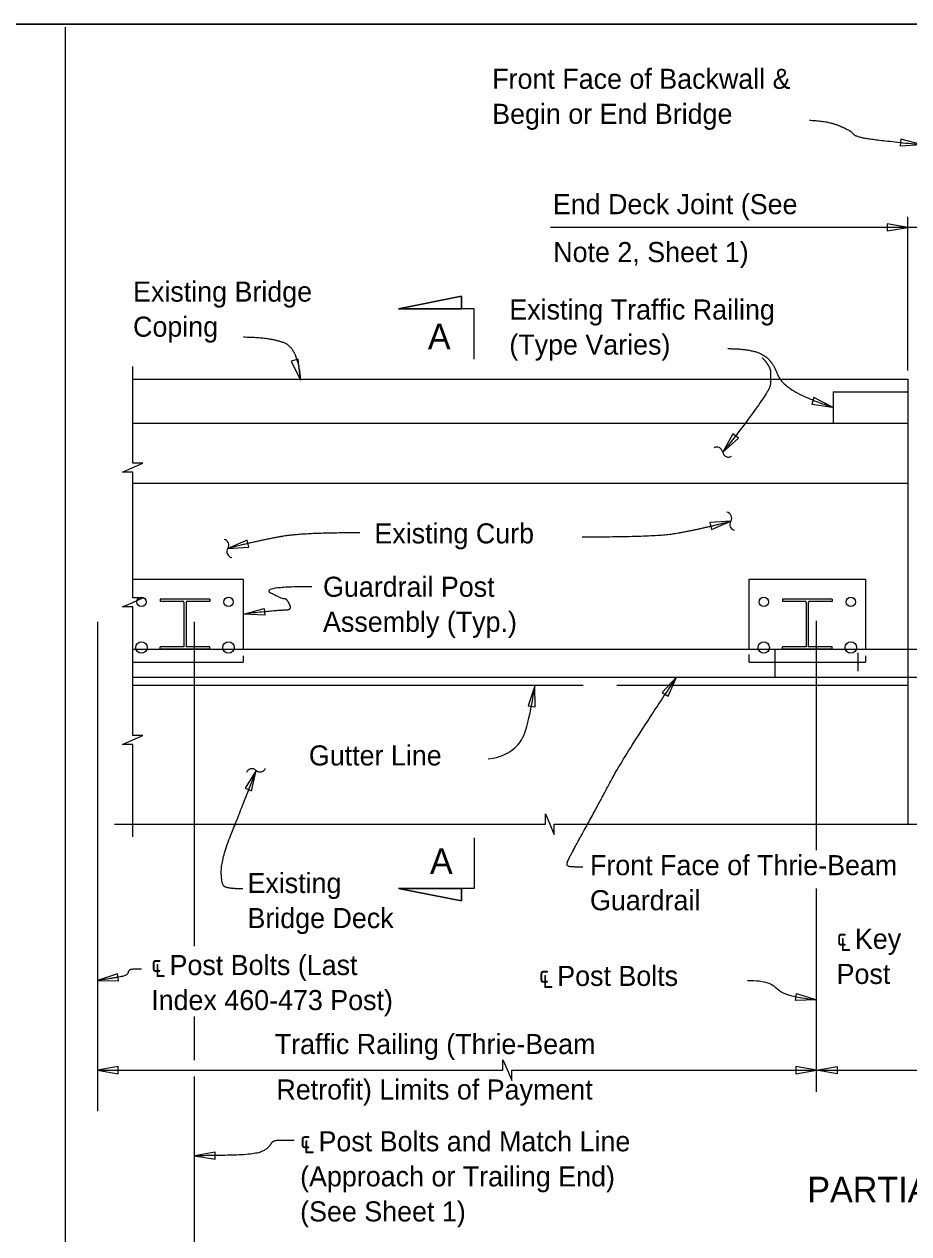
# Model space of a CAD drawing. Extents: x 0 to 41.1, y 0 to 25.9.
# Drawn here: x 18.69 to 27.57, y 13.8 to 25.95 of the extents above; entities that cross this region are included whole.
import ezdxf

# ---------------------------------------------------------------- set-up
doc = ezdxf.new("R2010")
doc.units = 0
for name, color, linetype in [('Dimension', 7, 'Continuous'), ('ExistSuperStruct', 7, 'Continuous'), ('Miscellaneous', 7, 'Continuous'), ('Miscellaneous1', 7, 'Continuous'), ('SteelMisc', 7, 'Continuous'), ('TextStructures', 7, 'Continuous')]:
    doc.layers.add(name, color=color, linetype=linetype)

msp = doc.modelspace()

# ---------------------------------------------------------------- linework, layer by layer
at = {"layer": 'Dimension'}
for p, q in [((19.1, 25.915), (19.1, -0.024)), ((27.565, 22.467), (27.565, 24.011)), ((28.073, 23.906), (23.974, 23.906)), ((22.45, 23.088), (23.083, 23.215)), ((23.083, 23.215), (23.083, 23.088)), ((23.209, 23.088), (22.45, 23.088)), ((23.209, 22.582), (23.209, 23.088)), ((26.646, 17.652), (26.646, 19.956)), ((23.209, 17.774), (23.209, 17.268)), ((23.209, 17.268), (22.45, 17.268)), ((22.45, 17.268), (23.083, 17.141)), ((23.083, 17.141), (23.083, 17.268)), ((26.646, 15.226), (26.646, 17.265))]:
    msp.add_line(p, q, dxfattribs=at)
for points in [[(0, 0), (41.051, 0), (41.051, 25.946), (0, 25.946)], [(27.697, 24.737), (27.494, 24.793), (27.487, 24.723)], [(27.565, 23.906), (27.357, 23.942), (27.357, 23.871)], [(23.083, 23.088), (23.083, 23.215), (22.45, 23.088)], [(21.464, 22.371), (21.44, 22.581), (21.372, 22.561)], [(26.808, 22.1), (26.621, 22.198), (26.599, 22.13)], [(25.706, 21.648), (25.863, 21.79), (25.807, 21.833)], [(25.786, 20.954), (25.575, 20.941), (25.591, 20.872)], [(20.735, 20.682), (20.946, 20.695), (20.93, 20.764)], [(20.897, 20.023), (21.1, 20.08), (21.108, 20.01)], [(25.242, 19.39), (25.098, 19.236), (25.157, 19.197)], [(23.818, 19.302), (23.751, 19.102), (23.821, 19.091)], [(21.019, 18.453), (20.909, 18.273), (20.974, 18.247)], [(23.083, 17.268), (23.083, 17.141), (22.45, 17.268)], [(19.425, 16.342), (19.637, 16.339), (19.626, 16.409)], [(26.647, 16.147), (26.436, 16.141), (26.446, 16.211)], [(19.425, 15.443), (19.634, 15.407), (19.634, 15.478)], [(26.646, 15.443), (26.438, 15.478), (26.438, 15.407)], [(26.646, 15.443), (26.854, 15.478), (26.854, 15.407)], [(20.399, 14.583), (20.607, 14.548), (20.607, 14.618)]]:
    msp.add_lwpolyline(points, close=True, dxfattribs=at)
for points in [[(19.779, 20.979), (19.779, 21.448), (19.676, 21.448), (19.779, 21.493), (19.882, 21.538), (19.779, 21.538), (19.779, 22.507)], [(19.779, 19.231), (19.779, 20.095), (19.676, 20.095), (19.779, 20.14), (19.882, 20.185), (19.779, 20.185), (19.779, 20.979)], [(19.779, 17.784), (19.779, 18.713), (19.676, 18.713), (19.779, 18.758), (19.882, 18.803), (19.779, 18.803), (19.779, 19.676)], [(19.595, 17.912), (23.924, 17.912), (23.924, 18.016), (23.969, 17.912), (24.014, 17.809), (24.014, 17.912), (26.975, 17.912)], [(26.975, 17.913), (31.853, 17.913), (31.853, 18.016), (31.898, 17.913), (31.943, 17.809), (31.943, 17.913), (34.208, 17.913)], [(19.425, 15.443), (23.498, 15.443), (23.498, 15.546), (23.543, 15.443), (23.588, 15.339), (23.588, 15.443), (35.521, 15.443)]]:
    msp.add_lwpolyline(points, dxfattribs=at)
for centre, start, end in [((25.646, 21.64), 8.6098, 120.3371), ((25.764, 21.658), 188.6098, 300.337), ((25.736, 20.987), 327.2252, 78.9524), ((25.836, 20.922), 147.2252, 258.9524), ((20.685, 20.714), 327.2252, 78.9524), ((20.785, 20.649), 147.2252, 258.9524), ((20.977, 18.409), 47.1839, 158.9112), ((21.058, 18.497), 227.1839, 338.9112)]:
    msp.add_arc(centre, 0.0596, start, end, dxfattribs=at)
for points, degree in [([(26.576, 24.982), (26.76, 24.975), (26.998, 24.876), (27.031, 24.817), (27.301, 24.777), (27.697, 24.737)], 2), ([(20.893, 22.805), (21.133, 22.805), (21.441, 22.701), (21.464, 22.371)], 2), ([(26.103, 22.598), (26.185, 22.505), (26.185, 22.408), (26.185, 22.254), (25.706, 21.648)], 2), ([(25.757, 22.688), (25.968, 22.688), (26.197, 22.591), (26.317, 22.259), (26.808, 22.1)], 2), ([(24.293, 20.798), (25.007, 20.798), (25.412, 20.86), (25.786, 20.954)], 2), ([(22.062, 20.838), (21.514, 20.838), (21.109, 20.776), (20.735, 20.682)], 2), ([(21.579, 20.297), (21.055, 20.297), (21.279, 20.175), (21.322, 20.183), (21.383, 20.061), (21.24, 20.061), (20.897, 20.023)], 2), ([(24.301, 17.481), (24.188, 17.481), (24.125, 17.496), (24.195, 17.634), (24.478, 18.15), (24.715, 18.596), (25.242, 19.39)], 2), ([(23.351, 18.569), (23.484, 18.584), (23.661, 18.681), (23.749, 18.857), (23.818, 19.302)], 3), ([(20.885, 17.263), (20.733, 17.263), (20.669, 17.309), (20.669, 17.567), (20.878, 18.083), (21.019, 18.453)], 2), ([(19.867, 16.458), (19.802, 16.457), (19.738, 16.451), (19.728, 16.394), (19.602, 16.369), (19.425, 16.342)], 2), ([(25.954, 16.343), (26.035, 16.343), (26.194, 16.332), (26.271, 16.223), (26.413, 16.18), (26.647, 16.147)], 3), ([(21.402, 14.735), (21.282, 14.735), (21.183, 14.735), (21.141, 14.654), (21.006, 14.594), (20.561, 14.583), (20.399, 14.583)], 2)]:
    msp.add_open_spline(points, degree=degree, dxfattribs=at)
at = {"layer": 'ExistSuperStruct'}
for p, q in [((27.565, 22.378), (19.779, 22.378)), ((27.565, 22.381), (27.565, 17.912)), ((26.815, 22.253), (27.565, 22.253)), ((19.779, 21.941), (27.565, 21.941)), ((19.779, 21.337), (27.565, 21.337)), ((19.779, 19.307), (24.305, 19.307)), ((24.641, 19.307), (27.565, 19.307))]:
    msp.add_line(p, q, dxfattribs=at)
msp.add_lwpolyline([(26.815, 22.253), (26.815, 21.941)], dxfattribs=at)
at = {"layer": 'Miscellaneous'}
for p, q in [((19.425, 19.946), (19.425, 15.032)), ((20.399, 16.688), (20.399, 19.946)), ((26.232, 19.39), (26.232, 19.671)), ((26.232, 19.671), (39.779, 19.671)), ((27.065, 19.448), (27.065, 19.633)), ((26.232, 19.39), (39.617, 19.39)), ((20.399, 15.543), (20.399, 15.981)), ((20.399, 8.681), (20.399, 15.38))]:
    msp.add_line(p, q, dxfattribs=at)
for points in [[(19.779, 19.541), (20.888, 19.541)], [(25.972, 19.541), (27.138, 19.541)]]:
    msp.add_lwpolyline(points, dxfattribs=at)
at = {"layer": 'Miscellaneous1'}
msp.add_lwpolyline([(0, 25.946), (41.051, 25.946), (41.051, 0), (0, 0)], close=True, dxfattribs=at)
at = {"layer": 'SteelMisc'}
for p, q in [((20.555, 20.171), (20.055, 20.171)), ((20.055, 20.171), (20.055, 20.15)), ((20.555, 20.171), (20.555, 20.15)), ((26.805, 20.171), (26.305, 20.171)), ((26.305, 20.171), (26.305, 20.15)), ((26.805, 20.171), (26.805, 20.15)), ((20.284, 20.15), (20.055, 20.15)), ((20.294, 20.14), (20.294, 19.692)), ((20.315, 20.14), (20.315, 19.692)), ((20.555, 20.15), (20.326, 20.15)), ((26.534, 20.15), (26.305, 20.15)), ((26.544, 20.14), (26.544, 19.692)), ((26.565, 20.14), (26.565, 19.692)), ((26.805, 20.15), (26.576, 20.15)), ((20.294, 19.692), (20.055, 19.692)), ((20.055, 19.671), (20.055, 19.692)), ((20.555, 19.692), (20.315, 19.692)), ((20.555, 19.671), (20.555, 19.692)), ((26.544, 19.692), (26.305, 19.692)), ((26.305, 19.671), (26.305, 19.692)), ((26.805, 19.692), (26.565, 19.692)), ((26.805, 19.671), (26.805, 19.692)), ((19.779, 19.671), (26.232, 19.671)), ((20.555, 19.671), (20.055, 19.671)), ((26.805, 19.671), (26.305, 19.671)), ((19.779, 19.39), (26.232, 19.39))]:
    msp.add_line(p, q, dxfattribs=at)
for points in [[(19.779, 20.374), (20.888, 20.374), (20.888, 19.676)], [(25.972, 19.676), (25.972, 20.374), (27.138, 20.374), (27.138, 19.669)], [(20.888, 19.602), (20.888, 19.541)], [(25.972, 19.541), (25.972, 19.618)], [(27.138, 19.602), (27.138, 19.541)]]:
    msp.add_lwpolyline(points, dxfattribs=at)
for centre, radius in [((19.867, 20.145), 0.0469), ((20.742, 20.145), 0.0469), ((26.117, 20.145), 0.0469), ((26.992, 20.145), 0.0469), ((19.867, 19.687), 0.0573), ((20.742, 19.687), 0.0573), ((26.117, 19.687), 0.0573), ((26.992, 19.687), 0.0573)]:
    msp.add_circle(centre, radius, dxfattribs=at)
for centre, start, end in [((20.284, 20.14), 0, 90), ((20.326, 20.14), 90, 180), ((26.534, 20.14), 0, 90), ((26.576, 20.14), 90, 180)]:
    msp.add_arc(centre, 0.0104, start, end, dxfattribs=at)

# ---------------------------------------------------------------- texts
at = {"layer": 'Dimension'}
for s, p in [('Front Face of Backwall &', (23.39, 25.297)), ('Begin or End Bridge', (23.39, 24.945)), ('Existing Bridge ', (19.783, 23.16)), ('Existing Traffic Railing', (23.562, 22.98)), ('Coping ', (19.783, 22.808)), ('(Type Varies)', (23.562, 22.628)), ('Guardrail Post ', (21.691, 20.196)), ('Assembly (Typ.)', (21.691, 19.844)), ('Front Face of Thrie-Beam ', (24.372, 17.4)), ('Existing ', (20.932, 17.221)), ('Guardrail', (24.372, 17.048)), ('Bridge Deck', (20.932, 16.869)), ('℄ Post Bolts (Last ', (19.965, 16.397)), ('Index 460-473 Post)', (19.965, 16.045)), ('Traffic Railing (Thrie-Beam', (21.206, 15.604)), ('Retrofit) Limits of Payment', (21.223, 15.147)), ('℄ Post Bolts and Match Line ', (21.461, 14.627)), ('(Approach or Trailing End)', (21.461, 14.275)), ('(See Sheet 1)', (21.461, 13.923))]:
    msp.add_text(s, height=0.2016, dxfattribs=at).set_placement(p)
at = {"layer": 'TextStructures'}
for s, height, p in [('End Deck Joint (See', 0.2016, (23.999, 24.038)), ('Note 2, Sheet 1)', 0.2016, (24.003, 23.557)), ('A', 0.256, (22.744, 22.682)), ('Existing Curb', 0.2016, (22.207, 20.732)), ('Gutter Line', 0.2016, (21.549, 18.502)), ('A', 0.256, (22.765, 17.413)), ('℄ Key ', 0.2016, (26.849, 16.66)), ('℄ Post Bolts', 0.2016, (23.859, 16.288)), ('Post', 0.2016, (26.849, 16.308)), ('PARTIAL PLAN OF RAILING', 0.256, (26.555, 14.116))]:
    msp.add_text(s, height=height, dxfattribs=at).set_placement(p)

doc.saveas('drawing.dxf')
